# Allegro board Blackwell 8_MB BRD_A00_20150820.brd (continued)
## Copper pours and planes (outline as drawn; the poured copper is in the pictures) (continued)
+VSDIO on L2: 101.84,175.46 101.33,175.46 100.19,174.32 100.19,171.14 101.97,169.36 101.97,160.35 102.35,159.96 102.35,158.19 102.6,157.93 103.24,157.93 103.62,158.31 103.62,162 103.11,162.5 103.11,170.12 101.33,171.9 101.33,173.93 102.09,174.7 102.09,175.2
+VSYS on TOP: 92.57,117.93 91.68,118.82 91.68,124.15 91.81,124.28 93.2,124.28 93.46,124.02 93.46,123.39 93.84,123.01 95.24,123.01 95.62,123.39 95.62,123.9 96.25,124.53 104.38,124.53 105.02,125.17 105.02,134.44 104.51,134.95 104.51,145.36 104,145.87 98.92,145.87 98.79,145.99 98.79,148.41 98.92,148.53 102.09,148.53 102.35,148.79 102.35,149.55 102.09,149.8 94.73,149.8 93.59,148.66 93.08,148.66 92.57,148.15 92.57,146.76 92.32,146.5 92.32,146.25 92.44,146.12 92.95,146.12 92.95,145.61 91.55,145.61 91.3,145.87 91.3,147.01 91.05,147.26 91.05,148.53 93.46,150.95 104.13,150.95 104.51,151.33 104.51,158.19 106.29,159.96 106.29,160.22 106.67,160.6 107.17,160.6 107.3,160.73 110.1,160.73 111.24,159.58 111.24,138.63 112.13,137.74 112.13,132.91 112.51,132.53 113.27,132.53 114.16,131.64 114.16,121.48 111.49,118.82 100.95,118.82 100.06,117.93 ; 18 cut-outs
+VSYS on TOP: 103.52,53.13 103.39,53.26 103.39,54.66 103.44,54.71 105.62,54.71 105.8,54.88 107.94,54.88 108.01,54.81 108.01,53.21 107.94,53.13 ; 4 cut-outs
+VSYS on L7: 109.33,53.26 109.33,73.22 107.56,75 107.56,78.68 108.19,79.32 108.19,90.5 107.56,91.13 107.56,120.09 107.05,120.59 105.65,120.59 105.14,120.09 105.14,88.59 106.03,87.7 106.03,86.43 105.78,86.18 105.78,83.51 106.03,83.26 106.03,82.37 105.14,81.48 105.14,73.6 106.54,72.21 106.54,67.64 106.86,67.32 106.86,53.16 109.23,53.16
+VUSB_5V_19V on TOP: 88.25,81.35 88.12,81.48 88.12,82.88 88.89,82.88 89.01,83 89.01,83.76 89.14,83.89 90.54,83.89 90.54,82.75 89.65,81.86 89.65,81.35 ; 3 cut-outs
+VUSB_5V_19V on TOP: 111.49,14.04 111.37,14.17 111.37,18.36 111.11,18.61 111.11,19.38 110.98,19.5 110.6,19.5 110.6,19.76 110.73,19.88 110.98,19.88 111.11,20.01 111.11,20.26 111.24,20.39 112.36,20.39 112.36,18.66 113.4,17.62 113.4,16.33 113.14,16.07 113.14,14.42 112.76,14.04 ; 2 cut-outs
+VUSB_5V_19V on TOP: 110.73,22.93 110.6,23.06 110.6,23.82 110.35,24.07 110.35,25.6 110.6,25.85 111.75,25.85 111.87,25.73 111.87,25.47 112,25.34 112,24.2 111.75,23.95 111.11,23.95 110.98,23.82 110.98,23.06 110.86,22.93 ; 2 cut-outs
+VUSB_5V_19V on BOTTOM: 110.22,11.25 110.03,11.44 110.03,12.83 111.37,14.17 111.37,22.68 110.6,23.44 110.6,24.96 110.73,25.09 112.13,25.09 113.52,23.69 113.52,13.28 111.49,11.25
+VUSB_5V_19V on L2: 110.73,23.06 111.11,23.06 112.13,24.07 112.13,24.71 111.75,25.09 111.24,25.09 110.98,24.84 110.98,24.2 110.6,23.82 110.6,23.19
+VUSB_5V_19V on L7: 105.9,8.33 109.59,8.33 110.73,9.47 110.73,9.53 110.79,9.53 113.4,12.14 113.4,23.31 111.62,25.09 110.86,25.09 110.6,24.84 110.6,24.07 111.37,23.31 111.37,14.04 109.59,12.26 107.94,12.26 107.68,12.52 107.3,12.52 107.17,12.39 107.17,11.76 106.67,11.25 105.9,11.25 105.78,11.12 103.24,11.12 102.98,11.37 100.77,11.37 98.03,8.63 98.03,6.01 98.17,5.88 98.5,5.88 98.54,5.84 98.94,5.84 99,5.89 99,6.47 99.17,6.65 100.9,6.65 101.13,6.42 101.13,5.84 102.04,5.84 102.25,6.04 102.25,6.32 102.98,7.06 103.62,7.06 104.25,7.69 105.27,7.69
ANT1_GND on TOP: 115.81,28.17 115.81,29.49 114.71,29.49 114.71,30 116.11,30 116.11,29.98 116.32,29.98 116.32,28.17
AUD_AGND on TOP: 85.08,193.62 84.57,194.13 84.57,195.52 84.44,195.65 81.77,195.65 80.33,197.1 80.33,206.9 79.97,206.9 79.74,207.13 79.74,207.79 82.81,207.79 82.81,198.6 83.56,197.63 84.69,198.09 89.35,198.09 90.48,197.63 91.23,198.6 91.23,200.89 91.32,200.89 92.53,202.1 91.32,203.31 91.23,203.31 91.23,207.79 95.67,207.79 97.65,205.81 103.62,205.81 106.67,202.76 106.67,199.84 106.03,199.21 104.13,199.21 104.13,200.99 103.87,201.24 99.55,201.24 99.17,200.86 99.17,198.32 98.28,198.32 97.52,197.56 96.89,197.56 96.13,196.79 95.87,196.79 92.95,193.87 89.65,193.87 89.39,193.62
AUD_AGND on BOTTOM: 85.08,193.62 84.57,194.13 84.57,195.52 84.44,195.65 81.77,195.65 80.12,197.3 80.12,207.79 82.81,207.79 82.81,198.6 83.56,197.63 84.69,198.09 89.35,198.09 90.48,197.63 91.23,198.6 91.23,200.89 91.32,200.89 92.53,202.1 91.32,203.31 91.23,203.31 91.23,204.74 91.3,204.67 92.57,204.67 93.33,203.91 93.33,203.14 93.97,202.51 95.24,202.51 95.62,202.13 95.62,200.86 95.74,200.73 96.38,200.73 96.51,200.6 96.51,197.81 96.25,197.56 95.74,197.56 95.62,197.68 94.86,197.68 94.86,195.78 94.47,195.4 94.22,195.4 94.22,195.27 93.97,195.02 93.59,195.02 93.46,194.89 93.46,194.38 92.7,193.62 ; 8 cut-outs
AUD_AGND on L2: 80,197.56 80,207.79 82.81,207.79 82.81,198.6 83.56,197.63 84.69,198.09 89.35,198.09 90.48,197.63 91.23,198.6 91.23,200.89 91.32,200.89 92.53,202.1 91.32,203.31 91.23,203.31 91.23,207.79 94.35,207.79 94.35,207.72 95.74,207.72 97.65,205.81 103.62,205.81 106.67,202.76 106.67,199.84 106.03,199.21 104.13,199.21 104.13,200.99 103.87,201.24 99.55,201.24 99.17,200.86 99.17,198.32 98.28,198.32 97.52,197.56 96.89,197.56 96.13,196.79 95.87,196.79 92.7,193.62 85.08,193.62 84.57,194.13 84.57,195.52 84.44,195.65 81.77,195.65 80.25,197.18 80.25,197.43 80.12,197.56
AUD_AGND on L3SGND: 85.08,193.62 84.57,194.13 84.57,195.52 84.44,195.65 81.77,195.65 80,197.43 80,207.34 79.54,207.79 82.81,207.79 82.81,198.6 83.56,197.63 84.69,198.09 89.35,198.09 90.03,197.61 90.85,197.81 91.13,198.16 91.23,198.6 91.23,200.89 91.32,200.89 92.53,202.1 91.32,203.31 91.23,203.31 91.23,207.79 95.67,207.79 97.65,205.81 103.62,205.81 106.67,202.76 106.67,199.84 106.03,199.21 104.13,199.21 104.13,200.99 103.87,201.24 99.55,201.24 99.17,200.86 99.17,198.32 98.28,198.32 97.52,197.56 96.89,197.56 96.13,196.79 95.87,196.79 92.7,193.62
AUD_AGND on L4SGND: 85.08,193.62 84.57,194.13 84.57,195.52 84.44,195.65 81.77,195.65 80.33,197.1 80.33,206.62 79.16,207.79 82.81,207.79 82.81,198.6 83.56,197.63 84.69,198.09 89.35,198.09 90.48,197.63 91.23,198.6 91.23,200.89 91.32,200.89 92.53,202.1 91.32,203.31 91.23,203.31 91.23,207.79 95.67,207.79 97.65,205.81 103.62,205.81 106.67,202.76 106.67,199.84 106.03,199.21 104.13,199.21 104.13,200.99 103.87,201.24 99.55,201.24 99.17,200.86 99.17,198.32 98.28,198.32 97.52,197.56 96.89,197.56 96.13,196.79 95.87,196.79 92.7,193.62
AUD_AGND on L5: 85.08,193.62 84.57,194.13 84.57,195.52 84.44,195.65 81.77,195.65 80.12,197.3 80.12,207.79 82.81,207.79 82.81,198.6 83.56,197.63 84.69,198.09 89.35,198.09 90.48,197.63 91.23,198.6 91.23,200.89 91.32,200.89 92.53,202.1 91.32,203.31 91.23,203.31 91.23,207.79 95.54,207.79 97.52,205.81 103.24,205.81 103.49,205.56 103.49,204.92 103.36,204.8 99.94,204.8 99.43,204.29 99.43,203.4 99.68,203.14 101.97,203.14 102.73,203.91 105.4,203.91 106.67,202.64 106.67,200.1 105.78,199.21 104.51,199.21 104.25,199.46 104.25,200.86 103.75,201.37 99.55,201.37 99.55,201.24 99.17,200.86 99.17,198.32 98.28,198.32 97.52,197.56 96.89,197.56 96.13,196.79 95.87,196.79 92.7,193.62
AUD_AGND on L6SGND: 85.08,193.62 84.57,194.13 84.57,195.52 84.44,195.65 81.77,195.65 80.33,197.1 80.33,206.12 78.73,207.71 78.73,207.79 82.81,207.79 82.81,198.6 83.56,197.63 84.69,198.09 89.35,198.09 90.48,197.63 91.23,198.6 91.23,200.89 91.32,200.89 92.53,202.1 91.32,203.31 91.23,203.31 91.23,207.79 95.67,207.79 97.65,205.81 103.62,205.81 106.67,202.76 106.67,199.84 106.03,199.21 104.13,199.21 104.13,200.99 103.87,201.24 99.55,201.24 99.17,200.86 99.17,198.32 98.28,198.32 97.52,197.56 96.89,197.56 96.13,196.79 95.87,196.79 92.7,193.62
AUD_AGND on L7: 85.08,193.62 84.57,194.13 84.57,195.52 84.44,195.65 81.77,195.65 80.12,197.3 80.12,207.79 82.81,207.79 82.81,198.6 83.56,197.63 84.69,198.09 89.35,198.09 90.48,197.63 91.23,198.6 91.23,200.89 91.32,200.89 92.53,202.1 91.32,203.31 91.23,203.31 91.23,207.79 95.67,207.79 97.65,205.81 103.62,205.81 106.67,202.76 106.67,199.84 106.03,199.21 104.13,199.21 104.13,200.99 103.87,201.24 99.55,201.24 99.17,200.86 99.17,198.32 98.28,198.32 97.52,197.56 96.89,197.56 96.13,196.79 95.87,196.79 92.7,193.62
BL_SW on TOP: 102.09,46.78 101.99,46.88 101.99,48.48 102.12,48.61 104.1,48.61 104.2,48.71 104.2,49.88 103.92,50.16 102.98,50.16 102.32,50.82 102.32,51.96 102.45,52.09 103.21,52.09 103.72,52.6 105.62,52.6 105.8,52.42 105.8,51.48 106.41,50.87 106.41,47.92 105.27,46.78
BQ24770_AGND on L7: 90.03,95.32 96.51,95.32 97.78,96.59 97.78,99.13 97.52,99.39 96.89,99.39 96.25,98.75 90.54,98.75 89.78,97.99 89.78,95.58
CODEC_MICVDD on BOTTOM: 99.17,203.02 99.05,203.14 99.05,205.3 99.17,205.43 99.55,205.43 99.68,205.3 99.68,203.02
CODEC_SPKVDD on BOTTOM: 99.81,193.62 99.68,193.75 99.68,195.27 99.81,195.4 99.81,196.16 100.06,196.16 100.06,195.4 100.32,195.14 101.08,195.14 101.33,195.4 101.33,196.16 101.59,196.16 101.59,195.27 101.97,194.89 101.97,193.62 ; 3 cut-outs
HP_RING_1 on BOTTOM: 92.49,205.05 91.25,206.29 91.25,207.64 91.36,207.75 92.4,207.75 93.46,206.7 95.62,206.7 96,206.32 96,205.3 95.62,205.3 95.36,205.05 ; 2 cut-outs
HP_SLEEVE on BOTTOM: 98.03,200.73 97.9,200.86 95.87,200.86 95.74,200.99 95.74,201.75 95.87,201.87 98.28,201.87 99.17,200.99 99.17,200.73 ; 2 cut-outs
HP_SLEEVE_1 on BOTTOM: 85.33,195.14 85.2,195.27 85.2,195.78 85.33,195.91 86.47,195.91 86.6,195.78 86.6,195.4 86.35,195.14
LCDBL_LED_A on TOP: 98.72,46.71 98.54,46.88 98.54,49.96 98.72,50.13 99.68,50.13 99.83,50.29 99.83,50.97 99.86,51 100.14,51 100.14,50.41 100.24,50.31 100.24,48.53 100.39,48.38 101.51,48.38 101.64,48.25 101.64,46.91 101.43,46.71 ; 1 cut-out
LCDBL_LED_A on BOTTOM: 89.37,39.03 89.24,39.16 89.24,40.03 89.34,40.13 91.96,40.13 92.14,39.95 93.08,39.95 93.15,40.03 93.59,40.03 93.69,39.92 93.69,39.36 93.59,39.26 93.13,39.26 93.05,39.34 90.38,39.34 90.08,39.03
LCDBL_LED_A on L2: 93.59,39.06 96.13,39.06 97.29,40.23 97.29,40.99 98.28,41.98 98.28,44.22 100.49,46.43 100.49,47.75 100.34,47.9 99.17,47.9 98.94,47.67 98.94,46.58 96.76,44.39 96.76,42.2 96.04,41.47 96.04,40.75 95.38,40.09 95.36,40.1 90.97,40.1 90.77,39.9 90.77,39.57 91.2,39.14 93.53,39.14 93.59,39.09
LCM_VDD on TOP: 90.23,46.93 90.16,47.01 90.16,49.17 90.54,49.55 90.77,49.55 90.87,49.65 90.87,50.13 90.94,50.21 91.53,50.21 91.65,50.08 91.65,47.01 91.58,46.93 ; 7 cut-outs
LCM_VDD on BOTTOM: 89.37,46.91 89.27,47.01 89.27,47.85 89.34,47.92 90.28,47.92 90.56,48.2 92.92,48.2 92.92,47.32 91.43,47.32 91.02,46.91
LCM_VDD_V1P8A on BOTTOM: 87.49,48.08 86.35,49.22 86.35,52.27 85.97,52.65 85.97,54.94 86.22,55.19 87.24,55.19 87.36,55.06 87.36,53.28 87.87,52.78 87.87,50.24 89.39,48.71 90.16,48.71 90.41,48.97 92.95,48.97 92.95,48.46 92.82,48.33 90.54,48.33 90.28,48.08 ; 3 cut-outs
MICBIAS1 on BOTTOM: 99.12,201.24 98.36,202 96.63,202 95.62,203.02 95.62,203.78 95.74,203.91 96.13,203.91 97.14,202.89 98.74,202.89 99.6,202.03 99.6,201.24 ; 1 cut-out
MICBIAS2 on BOTTOM: 97.75,199.49 97.29,199.94 96.91,199.94 96.76,200.1 96.76,200.65 96.84,200.73 97.9,200.73 98.06,200.58 98.06,200.17 98.41,199.82 99.1,199.82 99.1,199.59 98.41,199.59 98.31,199.49 ; 1 cut-out
PS8713_3V3 on BOTTOM: 100.7,80.84 99.94,81.61 99.94,85.42 100.06,85.54 100.95,85.54 101.08,85.42 101.08,85.16 100.95,85.03 100.7,85.03 100.57,84.91 100.57,84.65 100.82,84.4 100.95,84.4 101.08,84.27 101.08,84.15 100.95,84.02 100.7,84.02 100.57,83.89 100.57,83.64 100.7,83.51 100.95,83.51 101.08,83.38 101.08,83.13 100.95,83 100.95,81.99 101.33,81.61 107.81,81.61 108.32,82.11 108.32,85.29 107.68,85.92 106.16,85.92 106.03,86.05 106.03,86.3 106.29,86.56 106.92,86.56 107.05,86.69 107.05,87.7 107.17,87.83 107.68,87.83 107.81,87.7 107.81,86.56 109.08,85.29 109.08,83.38 109.33,83.13 109.33,82.11 108.06,80.84 ; 7 cut-outs
PWR_AD on TOP: 87.31,85.85 87.18,85.97 87.18,86.43 87.06,86.56 84.72,86.56 84.59,86.69 84.59,89.99 84.72,90.11 89.52,90.11 89.65,89.99 89.65,88.95 89.7,88.89 89.7,88.41 89.67,88.39 88.56,88.39 88.43,88.26 88.43,85.92 88.35,85.85 ; 2 cut-outs
PWR_AD_B on TOP: 84.95,90.37 84.7,90.62 84.7,99.26 85.33,99.89 85.33,104.08 87.49,106.24 87.49,108.28 87.62,108.4 88.63,108.4 88.89,108.66 88.89,110.82 89.14,111.07 89.78,111.07 90.41,110.43 91.55,110.43 91.68,110.56 91.68,111.96 91.81,112.09 92.57,112.09 92.7,111.96 92.7,104.21 92.44,103.96 90.92,103.96 88.63,101.67 88.63,95.96 89.65,94.94 89.65,90.5 89.52,90.37 ; 6 cut-outs
PWR_BT_A on TOP: 95.36,126.82 94.98,127.2 91.81,127.2 91.55,127.45 91.55,128.85 92.57,129.87 98.03,129.87 98.28,129.61 98.28,127.71 98.16,127.58 97.52,127.58 96.76,126.82 ; 6 cut-outs
PWR_CHG_HG on TOP: 90.41,110.82 90.28,110.94 90.28,111.96 90.92,112.59 91.43,112.59 91.68,112.34 91.68,112.09 91.43,111.83 91.43,110.94 91.3,110.82
PWR_CHG_LG on TOP: 96.38,110.82 96.25,110.94 96.25,111.83 96.63,112.21 97.14,112.21 97.4,111.96 97.4,110.82
PWR_CHG_PH on TOP: 93.33,106.62 92.95,107.01 92.95,111.83 91.93,112.85 91.93,114.5 92.19,114.75 96.51,114.75 96.76,114.5 96.76,112.59 96,111.83 96,106.88 95.74,106.62
RF_WIFI_ANT_AUX_2 on TOP: 111.72,31.78 111.72,34.87 112.71,34.87 112.71,34.37 112.23,34.37 112.23,32.28 113.19,32.28 113.19,36.04 113.7,36.04 113.7,33.07 116.11,33.07 116.11,32.56 113.7,32.56 113.7,31.78
RF_WIFI_ANT_AUX_3 on TOP: 113.8,33.27 113.8,34.09 114.92,34.09 114.92,33.58 116.04,33.58 116.04,34.67 115.3,34.67 115.3,34.98 116.44,34.98 116.44,33.27
SAR_CSG on L7: 81.04,187.83 81.04,189.35 80.76,189.35 80.76,195.47 84.26,195.47 84.26,191.16 85.13,191.16 85.13,187.83
SND75DP130SS_3V3 on TOP: 97.65,65.96 97.52,66.09 97.52,67.51 97.93,67.91 99.05,67.91 99.05,68.78 99.94,68.78 99.94,66.87 99.43,66.37 98.54,66.37 98.13,65.96 ; 6 cut-outs
SPK_LN on BOTTOM: 89.14,22.93 89.01,23.06 89.01,24.58 88.89,24.71 88.51,24.71 88.38,24.84 88.38,25.34 88.51,25.47 89.14,25.47 89.27,25.34 89.9,25.34 90.03,25.22 90.03,23.06 89.9,22.93 ; 2 cut-outs
SPK_LN on L5: 100.2,195.97 100.75,195.42 100.75,194.89 100.47,194.61 99.63,194.61 99,195.24 99,195.73 99.24,195.97
SPK_LN_R on BOTTOM: 89.65,15.82 89.01,16.45 89.01,22.42 89.14,22.55 89.78,22.55 90.03,22.3 90.03,18.74 90.16,18.61 90.16,17.09 90.54,16.71 91.93,16.71 91.93,15.82
SPK_LP on BOTTOM: 90.41,22.93 90.28,23.06 90.28,25.22 90.41,25.34 90.92,25.34 91.05,25.47 91.81,25.47 91.93,25.34 91.93,24.71 91.81,24.58 91.43,24.58 91.3,24.46 91.3,23.06 91.17,22.93 ; 2 cut-outs
SPK_LP on L5: 100.16,197.3 98.56,197.3 98.32,197.06 98.32,196.32 98.39,196.26 100.16,196.26
SPK_LP_R on BOTTOM: 90.41,17.09 90.28,17.22 90.28,22.42 90.41,22.55 91.17,22.55 91.3,22.42 91.3,18.99 91.93,18.36 91.93,17.09
VGG_LX0 on BOTTOM: 98.69,165.68 98.69,166.82 99.5,166.82 99.66,166.97 99.66,168.02 99.66,168.02 99.66,168.24 99.67,168.24 99.67,169.43 99.17,169.92 99.17,172.33 99.3,172.46 99.3,172.59 99.38,172.66 99.5,172.66 99.55,172.61 99.55,170.71 100.91,169.35 100.91,168.51 100.98,168.45 100.98,165.68
VGG_LX1 on BOTTOM: 95.31,165.68 95.21,165.78 95.21,166.77 95.29,166.85 95.64,166.85 95.92,167.13 95.92,169.24 98.11,171.42 98.11,172.61 98.16,172.66 98.28,172.66 98.41,172.54 98.41,170.48 97.29,169.36 97.29,166.64 97.19,166.54 97.19,165.81 97.06,165.68
VGG_LX2 on BOTTOM: 93.18,165.76 93.13,165.81 93.13,169.01 96.42,172.3 97.15,172.3 97.29,172.44 97.29,172.59 97.37,172.66 97.47,172.66 97.55,172.59 97.55,172.18 94.54,169.17 94.54,167.09 94.73,166.9 94.91,166.9 95.01,166.8 95.01,165.86 94.91,165.76
VGG_LX3 on BOTTOM: 90.97,167.48 90.97,168.52 95.9,173.45 96.71,173.45 96.76,173.4 96.76,173.27 96.68,173.2 96.58,173.2 96.4,173.02 96.4,172.54 92.87,169.01 92.87,167.48
VNN_LX on BOTTOM: 90.79,173.96 90.79,175.86 96.68,175.86 96.76,175.79 96.76,175.28 96.68,175.2 94.58,175.2 93.33,173.96
VSIM1_PMU_R on BOTTOM: 112.75,97.24 112.61,97.38 112.61,97.61 112.97,97.96 112.97,98.88 112.79,99.05 112.33,99.05 112.23,99.16 112.23,99.63 112.24,99.63 112.36,99.74 112.79,99.74 113.12,100.07 113.35,100.07 113.52,99.89 113.52,97.58 113.18,97.24

Small or netless copper shapes (teardrops, artwork), in the pictures only: 1 on TOP, 3 on BOTTOM, 2 on L3SGND, 2 on L6SGND, 1 on L7

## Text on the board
Ref Des/Silkscreen Bottom: M1.6X2.5 | RTC | NFC | TP | AUX | M | PPID | SPK | BTY | LCD | X701:19.2MHZ | X703:32.768KHZ
Ref Des/Silkscreen Top: X1701:32.768KHZ | BLACKWELL T4 DVT2.1 MB | 14H30-1 | PWB:H4W2R | MADE IN TAIWAN | REV:A00
User.17: ID-LABEL-16-U
User.27: ByImpedance:100.0@_REF_L2=("3.0/7.5(L2)")|_REF_L1=("3.0/6.5(L1)")|_REF_L7=("3.0/7.5(L7)")|_REF_L4SGND=("2.4/7.2(L4SGND)")|Type="DP"|imp="100.0"|_REF_L5=("2.4/7.2(L5)")|_REF_L8=("3.0/6.5(L8)") | ByImpedance:37.0@_REF_L2=("7.0(L2)" "3.5(L2)")|_REF_L1=("7.0(L1)")|_REF_L7=("7.0(L7)" "3.5(L7)")|_REF_L4SGND=("4.5(L4SGND)" "5.0(L4SGND)")|Type="SE"|imp="37.0"|_REF_L5=("4.5(L5)" "5.0(L5)")|_REF_L8=("7.0(L8)") | ByImpedance:40.0@_REF_L2=("6.0(L2)" "3.0(L2)")|_REF_L1=("6.0(L1)")|_REF_L7=("6.0(L7)" "3.0(L7)")|_REF_L4SGND=("4.0(L4SGND)")|Type="SE"|imp="40.0"|_REF_L5=("4.0(L5)")|_REF_L8=("6.0(L8)") | ByImpedance:45.0@_REF_L2=("4.5(L2)" "2.4(L2)")|_REF_L1=("4.5(L1)")|_REF_L7=("4.5(L7)" "2.4(L7)")|_REF_L4SGND=("3.0(L4SGND)")|Type="SE"|imp="45.0"|_REF_L5=("3.0(L5)")|_REF_L8=("4.5(L8)") | ByImpedance:50.0@_REF_L2=("3.5(L2)")|_REF_L1=("11.0(L1)" "4.0(L1)")|_REF_L7=("3.5(L7)")|_REF_L4SGND=("2.6(L4SGND)")|Type="SE"|imp="50.0"|_REF_L5=("2.6(L5)")|_REF_L8=("11.0(L8)" "4.0(L8)") | ByImpedance:76.0@_REF_L2=("3.0/5.0(L2)" "5.0/4.5(L2)")|_REF_L1=("5.0/4.0(L1)")|_REF_L7=("3.0/5.0(L7)" "5.0/4.5(L7)")|_REF_L4SGND=("4.0/5.0(L4SGND)")|Type="DP"|imp="76.0"|_REF_L5=("4.0/5.0(L5)")|_REF_L8=("5.0/4.0(L8)") | ByImpedance:80.0@_REF_L2=("2.8/6.0(L2)" "4.5/5.0(L2)")|_REF_L1=("4.5/4.0(L1)")|_REF_L7=("2.8/6.0(L7)" "4.5/5.0(L7)")|_REF_L4SGND=("3.5/4.5(L4SGND)")|Type="DP"|imp="80.0"|_REF_L5=("3.5/4.5(L5)")|_REF_L8=("4.5/4.0(L8)") | ByImpedance:85.0@_REF_L2=("4.0/5.0(L2)" "2.4/5.5(L2)")|_REF_L1=("4.0/4.5(L1)")|_REF_L7=("4.0/5.0(L7)" "2.4/5.5(L7)")|_REF_L4SGND=("2.6/3.0(L4SGND)")|Type="DP"|imp="85.0"|_REF_L5=("2.6/3.0(L5)")|_REF_L8=("4.0/4.5(L8)") | ByImpedance:90.0@_REF_L2=("3.0/4.0(L2)")|_REF_L1=("3.5/4.5(L1)")|_REF_L7=("3.0/4.0(L7)")|_REF_L4SGND=("2.8/5.0(L4SGND)")|Type="DP"|imp="90.0"|_REF_L5=("2.8/5.0(L5)")|_REF_L8=("3.5/4.5(L8)") | LayerIndex:nil | Source:H8-0.8-8.xls | artWorks:("_REF_L5" "_REF_L4SGND" "_REF_L2" "_REF_L8" "_REF_L7" "_REF_L1") | gtImpOutlineUsed:BOARD GEOMETRY/PANEL_OUTLINE
User.28: Board Accuracy Check,Aug 20 10:17:57 2015,Passed | Dummy-Static-No Shape On Layer Check,Aug 20 10:17:57 2015,Passed | Split Plane Check,Apr 17 10:42:05 2015,Passed
User.30: M2X3 | AUX | M | M1.6X2.5 | RTC | SPK | X1701:32.768KHZ | X703:32.768KHZ | 14H30-SD | 448.05Y01.00SD | BLACKWELL T4 DVT MB | MADE IN TAIWAN
User.32: This gerber is just for your reference to find the DP impedance traces in layer L1. | DP IMPEDANCE TABLE: L1 | * - Denotes that this Impedance | is NOT used | IMP(Ohm) | *76.0 | *80.0 | 85.0 | *90.0 | *100.0 | WIDTH(mils) | 5.0/4.0 | 4.5/4.0 | 4.0/4.5 | 3.5/4.5 | 3.0/6.5 | TYPE | DP
User.34: This gerber is just for your reference to find the SE impedance traces in layer L1. | SE IMPEDANCE TABLE: L1 | * - Denotes that this Impedance | is NOT used | IMP(Ohm) | *37.0 | *40.0 | 45.0 | *50.0 | WIDTH(mils) | 7.0 | 6.0 | 4.5 | 11.0 | 4.0 | TYPE | SE
User.36: This gerber is just for your reference to find the DP impedance traces in layer L2. | DP IMPEDANCE TABLE: L2 | * - Denotes that this Impedance | is NOT used | IMP(Ohm) | *76.0 | *80.0 | *85.0 | 85.0 | *90.0 | *100.0 | WIDTH(mils) | 3.0/5.0 | 5.0/4.5 | 2.8/6.0 | 4.5/5.0 | 4.0/5.0 | 2.4/5.5 | 3.0/4.0 | 3.0/7.5 | TYPE | DP
User.38: This gerber is just for your reference to find the SE impedance traces in layer L2. | SE IMPEDANCE TABLE: L2 | * - Denotes that this Impedance | is NOT used | IMP(Ohm) | *37.0 | *40.0 | *45.0 | 45.0 | *50.0 | WIDTH(mils) | 7.0 | 3.5 | 6.0 | 3.0 | 4.5 | 2.4 | TYPE | SE
User.40: This gerber is just for your reference to find the DP impedance traces in layer L5. | DP IMPEDANCE TABLE: L5 | * - Denotes that this Impedance | is NOT used | IMP(Ohm) | *76.0 | *80.0 | 85.0 | *90.0 | *100.0 | WIDTH(mils) | 4.0/5.0 | 3.5/4.5 | 2.6/3.0 | 2.8/5.0 | 2.4/7.2 | TYPE | DP
User.42: This gerber is just for your reference to find the SE impedance traces in layer L5. | SE IMPEDANCE TABLE: L5 | * - Denotes that this Impedance | is NOT used | IMP(Ohm) | *37.0 | *40.0 | 45.0 | *50.0 | WIDTH(mils) | 4.5 | 5.0 | 4.0 | 3.0 | 2.6 | TYPE | SE
User.44: This gerber is just for your reference to find the DP impedance traces in layer L7. | DP IMPEDANCE TABLE: L7 | * - Denotes that this Impedance | is NOT used | IMP(Ohm) | *76.0 | *80.0 | *85.0 | 85.0 | *90.0 | *100.0 | WIDTH(mils) | 3.0/5.0 | 5.0/4.5 | 2.8/6.0 | 4.5/5.0 | 4.0/5.0 | 2.4/5.5 | 3.0/4.0 | 3.0/7.5 | TYPE | DP
User.45: Note:Refer to DRILL layer for ELLIPSE drill direction | FIGURE | SIZE | 10.0 | 4.0 | 8.0 | 16.0 | 18.0 | 28.0 | 79.0 | 103.0 | 32.0 | 34.0 | 36.0 | 42.0 | 46.0 | 52.0 | 65.0 | 86.0 | 158.0 | 48.0x24.0 | 52.0x24.0 | 58.0x24.0 | 63.0x24.0 | 91.0x24.0 | 91.0x52.0 | DRILL CHART: L2 to L3SGND | DRILL CHART: L3SGND to L6SGND | DRILL CHART: L5 to L6SGND | DRILL CHART: L6SGND to L7 | DRILL CHART: L7 to BOTTOM | DRILL CHART: TOP to BOTTOM | DRILL CHART: TOP to L2 | ALL UNITS ARE IN MILS | PLATED | NON-PLATED | QTY | 1052 | 1098 | 1241 | 2549 | 2965 | 654 | 789 | 104 | 34 | 2 | 7 | 1 | 6 | 4 | This gerber is just for your reference to find the DP impedance traces in layer L4SGND. | This gerber is just for your reference to find the DP impedance traces in layer L8. | This gerber is just for your reference to find the SE impedance traces in layer L4SGND. | This gerber is just for your reference to find the SE impedance traces in layer L7. | This gerber is just for your reference to find the SE impedance traces in layer L8. | DP IMPEDANCE TABLE: L4SGND | DP IMPEDANCE TABLE: L8 | SE IMPEDANCE TABLE: L4SGND | SE IMPEDANCE TABLE: L7 | SE IMPEDANCE TABLE: L8 | * - Denotes that this Impedance | is NOT used | Model | BLACKWELL T4 DVT2.1 MB | PCB_NO | 14H30 | VER. | Layer | DRILL_1_2 | DRILL_1_8 | DRILL_2_3 | DRILL_3_4 | DRILL_3_6 | DRILL_5_6 | DRILL_6_7 | DRILL_7_8 | L1 | L2 | L3SGND | L4SGND | TMASK | TPLACE | TSILK | TSMD | Designer | YIKI WANG | IMP(Ohm) | *37.0 | *76.0 | *40.0 | *80.0 | *85.0 | 45.0 | 85.0 | *45.0 | *50.0 | *90.0 | *100.0 | Date | 08/20/2015 | WIDTH(mils) | 7.0 | 3.5 | 6.0 | 4.5 | 11.0 | 3.0 | 2.4 | 5.0/4.0 | 4.5/4.0 | 5.0 | 4.0/4.5 | 3.5/4.5 | 2.6 | 3.0/6.5 | 4.0/5.0 | 2.6/3.0 | 2.8/5.0 | 2.4/7.2 | TYPE | SE | DP | BMASK | BPLACE | BSILK | BSMD | L5 | L6SGND | L7 | L8
